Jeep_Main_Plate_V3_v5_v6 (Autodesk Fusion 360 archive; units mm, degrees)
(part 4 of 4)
sketch "Sketch53" plane through (0, 0, 15) normal (0, 0, 1) x axis (-1, 0, 0)
  line L1 (15.267, 45.6587) -> (26.496, 50.1585)
  line L2 (10.534, 57.4447) -> (15.267, 45.6587)
  line L3 (8.8076, 61.7928) -> (10.534, 57.4447)
  line L4 (3.6528, 52.1791) -> (8.8076, 61.7928)
  line L5 (3.9887, 51.3411) -> (3.6528, 52.1791)
  line L6 (6.267, 45.6587) -> (3.9887, 51.3411)
  line L7 (6.2374, 45.6587) -> (6.267, 45.6587)
  line L8 (3.6428, 52.1605) -> (6.2374, 45.6587)
  line L9 (2.418, 49.8764) -> (3.6428, 52.1605)
  line L10 (-10.5895, 82.3184) -> (2.418, 49.8764)
  line L11 (2.3021, 78.0799) -> (-10.5895, 82.3184)
  line L12 (-2.2107, 89.3352) -> (2.3021, 78.0799)
  line L13 (-11.4211, 89.8) -> (-3.0554, 89.8)
  line L14 (-59, 89.8) -> (-11.4211, 89.8)
  line L15 (-62, 76.6) -> (-62, 86.8)
  line L16 (-60.8, 76.6) -> (-62, 76.6)
  line L17 (-60.8, 84.1) -> (-60.8, 76.6)
  line L18 (-43.8, 87.6) -> (-57.3, 87.6)
  line L19 (-5, 45) -> (0, 45)
  line L20 (-5, 43.8) -> (-5, 45)
  line L21 (14.4017, 43.8) -> (-5, 43.8)
  line L22 (26.8692, 48.153) -> (17.3111, 44.3207)
  line L23 (22.4016, 64.6773) -> (27.9812, 50.7537)
  line L24 (20.9164, 64.0822) -> (22.4016, 64.6773)
  line L25 (26.496, 50.1585) -> (20.9164, 64.0822)
  line L26 (15.274, 45.6587) -> (15.267, 45.6587)
  arc A1 centre (-3.0554, 88.8) radius 1 clockwise from (-3.0554, 89.8) to (-2.2107, 89.3352)
  arc A2 centre (-59, 86.8) radius 3 clockwise from (-62, 86.8) to (-59, 89.8)
  arc A3 centre (-54.6577, 81.4577) radius 6.6865 clockwise from (-60.8, 84.1) to (-57.3, 87.6)
  arc A4 centre (-49.0833, 38.3509) radius 49.5316 clockwise from (-43.8, 87.6) to (0, 45)
  arc A5 centre (14.4017, 52.3) radius 8.5 clockwise from (17.0909, 44.2366) to (14.4017, 43.8)
  arc A6 centre (14.613, 51.05) radius 7.25 clockwise from (17.3111, 44.3207) to (17.0909, 44.2366)
  arc A7 centre (26.1249, 50.0094) radius 2 clockwise from (27.9812, 50.7537) to (26.8692, 48.153)
  point P3 (15.267, 45.6587)
  point P43 (15.267, 45.6587)
  point P42 (15.274, 45.6587)
  point P44 (15.274, 45.6587)
  coincident P3 P43
  coincident P42 P44
  horizontal L26
fillet "Fillet9" radius 8
sketch "Sketch54" plane through (0, 0, 2) normal (0, 0, 1) x axis (-1, 0, 0)
  line L1 (22.399, 64.6763) -> (20.9164, 64.0822)
  line L2 (15.4823, 81.9273) -> (22.399, 64.6763)
  line L3 (-0.7632, 85.7539) -> (-2.1266, 89.1706)
  line L4 (2.3021, 78.0799) -> (-0.7632, 85.7539)
  line L5 (-10.5895, 82.3184) -> (2.3021, 78.0799)
  line L6 (2.418, 49.8764) -> (-10.5895, 82.3184)
  line L7 (8.8076, 61.7928) -> (2.418, 49.8764)
  line L8 (15.267, 45.6587) -> (8.8076, 61.7928)
  line L9 (26.496, 50.1585) -> (15.267, 45.6587)
  line L10 (20.9164, 64.0822) -> (26.496, 50.1585)
  line L11 (9.6902, 59.5882) -> (22.399, 64.6763)
  line L12 (-2.2324, 89.368) -> (9.6902, 59.5882)
  arc A1 centre (-1.6389, 67.3739) radius 22.4708 clockwise from (-3.0554, 89.8) to (15.4823, 81.9273)
  arc A2 centre (-3.0554, 88.8) radius 1 clockwise from (-3.0554, 89.8) to (-2.1266, 89.1706)
  point P3 (22.399, 64.6763)
  point P16 (22.399, 64.6763)
  point P17 (9.6902, 59.5882)
  point P18 (-2.2324, 89.368)
  coincident P3 P16
  coincident L8 P17
  perpendicular L8 L11
  coincident A2 P18
  perpendicular L11 L12
extrude "Extrude30" cut sketch "Sketch54" profile of L2 A1 A2 L3 L4 L5 L8 L11 L12 against normal blind 8
extrude "Extrude31" cut of existing geometry blind -7
delete_face "DeleteFace1"
delete_face "DeleteFace2"
extrude "Extrude32" add of existing geometry blind 7
extrude "Extrude33" add of existing geometry blind 0 (= "2.365E-05 mm")
delete_face "DeleteFace3"
extrude "Extrude34" add of existing geometry blind 1
fillet "Fillet10" radius 2
fillet "Fillet11" radius 1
